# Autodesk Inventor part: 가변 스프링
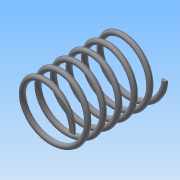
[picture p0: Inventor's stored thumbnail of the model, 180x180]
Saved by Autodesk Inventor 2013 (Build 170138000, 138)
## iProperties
Created: 2018-06
Part Number: 가변 스프링
Material: 일반
Document SubType Name: Modeling
Designer: Administrator
Density: 1 g/cm^3
Author: Administrator
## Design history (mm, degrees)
sketch "스케치1"
  geometry: L1 (0, 0)-(0, 73.25); L2 (0, 0)-(22.5, 0); L3 (0, 73.25)-(20.5, 73.25); C1 r 2 at (22.5, 0)
  constraints: 6 end point, 1 centre point, 1 coincident, 1 parallel, 1 perpendicular, 1 vertical
  dimensions: "d0" = 73.25 distance of L1.start L1.end (derived); "d1" = 22.5 distance of L1.start L2.end; "d2" = 4 diameter of C1
feature "코일1" sketch "스케치1" pitch "d3" = 10; turns "d5" = 6; dims "d4" = 73.25 (= d0), "d6" = 0, angle "d7" = 90 deg, angle "d8" = 90 deg, "d9" = 0, "d10" = 0
sketch "스케치2"
  geometry: L1 (0, -25)-(73.25, -25); L2 (73.25, -25)-(73.25, 25); L3 (73.25, 25)-(0, 25); L4 (0, 25)-(0, -25); 2 further points
  constraints: 8 end point, 2 coincident, 2 parallel, 1 horizontal, 1 midpoint, 1 perpendicular
  dimensions: "d11" = 73.25 distance of L3.end L2.end (derived); "d12" = 50 distance of L2.end L1.end
extrude "돌출1" sketch "스케치2" stored distance "d13" = 0; taper "d14" = 0 deg
node "솔리드1"
